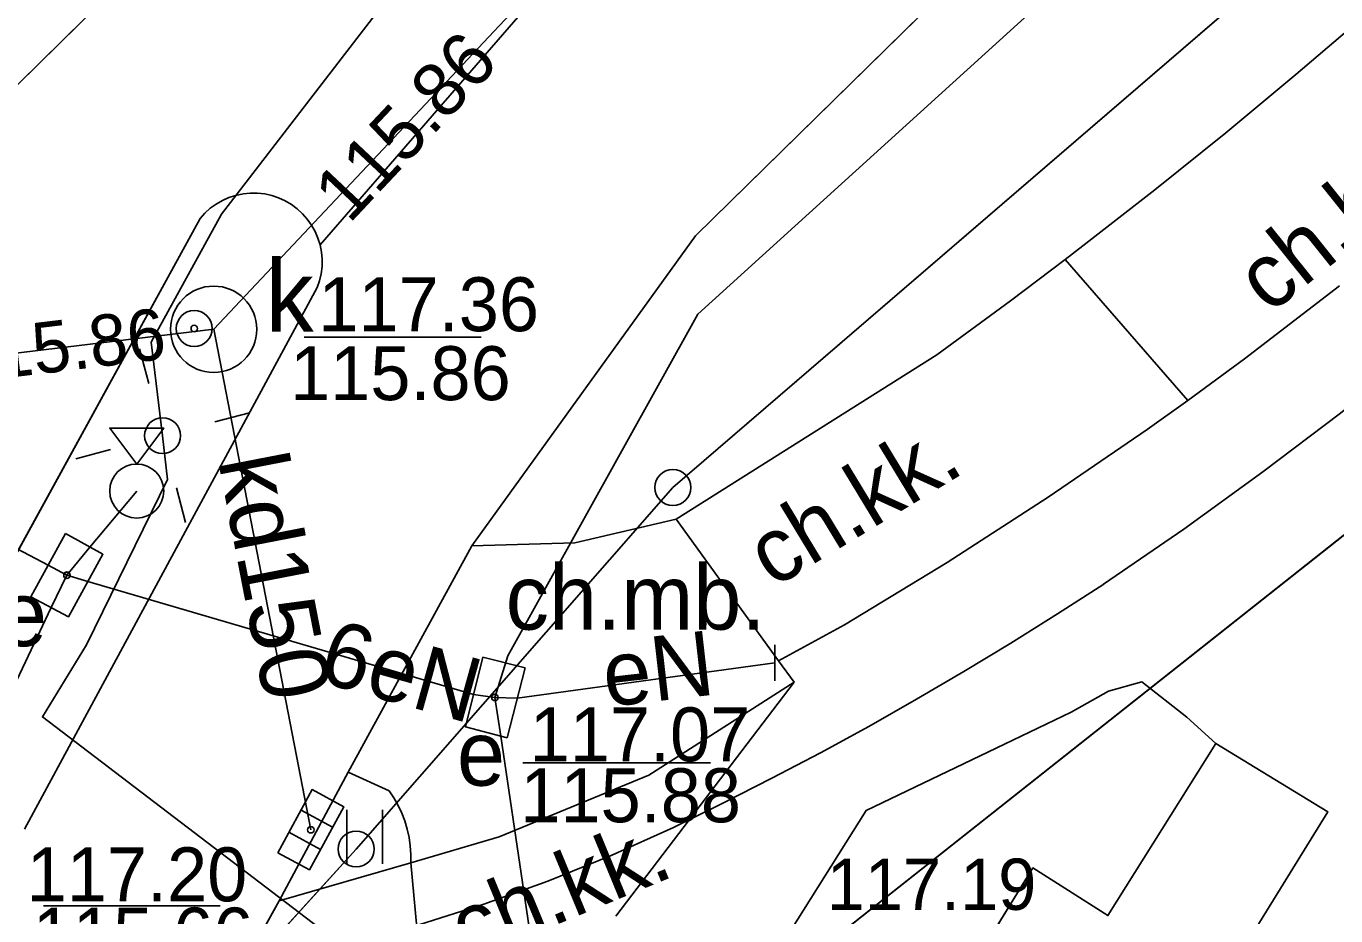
# Model space of a CAD drawing. Extents: x 6434771 to 6436222, y 5663454 to 5664782.
# Drawn here: x 6435500.32 to 6435518.53, y 5663756.44 to 5663768.81 of the extents above; entities that cross this region are included whole.
import ezdxf

# ---------------------------------------------------------------- set-up
doc = ezdxf.new("R2010")
doc.units = 0
for name, color, linetype in [('Warstwa 1', 7, 'Continuous'), ('Warstwa 10', 7, 'Continuous'), ('Warstwa 11', 7, 'Continuous'), ('Warstwa 12', 7, 'Continuous'), ('Warstwa 13', 7, 'Continuous'), ('Warstwa 14', 7, 'Continuous'), ('Warstwa 15', 7, 'Continuous'), ('Warstwa 2', 7, 'Continuous'), ('Warstwa 20', 7, 'Continuous'), ('Warstwa 37', 7, 'Continuous'), ('Warstwa 4', 7, 'Continuous'), ('Warstwa 40', 7, 'Continuous'), ('Warstwa 5', 7, 'Continuous'), ('Warstwa 6', 7, 'Continuous'), ('Warstwa 7', 7, 'Continuous'), ('Warstwa 8', 7, 'Continuous'), ('Warstwa 9', 7, 'Continuous')]:
    doc.layers.add(name, color=color, linetype=linetype)

msp = doc.modelspace()

# ---------------------------------------------------------------- linework, layer by layer
at = {"layer": 'Warstwa 1'}
for p, q in [((6435492.76, 5663760.678), (6435514.22, 5663781.8)), ((6435492.76, 5663760.678), (6435514.22, 5663781.8)), ((6435509.313, 5663762.399), (6435521.147, 5663772.588)), ((6435509.313, 5663762.399), (6435521.147, 5663772.588)), ((6435506.094, 5663751.807), (6435526.058, 5663767.608)), ((6435506.094, 5663751.807), (6435526.058, 5663767.608)), ((6435504.911, 5663757.372), (6435509.313, 5663762.399)), ((6435504.911, 5663757.372), (6435509.313, 5663762.399)), ((6435502.002, 5663754.167), (6435504.911, 5663757.372)), ((6435502.002, 5663754.167), (6435504.911, 5663757.372))]:
    msp.add_line(p, q, dxfattribs=at)
msp.add_lwpolyline([(6435511.034, 5663751.768), (6435514.319, 5663757.109), (6435515.361, 5663756.446), (6435516.861, 5663758.838), (6435518.419, 5663757.889), (6435513.645, 5663750.156)], close=True, dxfattribs=at)
at = {"layer": 'Warstwa 10'}
for centre in [(6435509.313, 5663762.399), (6435504.911, 5663757.372)]:
    msp.add_circle(centre, 0.25, dxfattribs=at)
at = {"layer": 'Warstwa 11'}
for points in [[(6435500.87, 5663761.76), (6435501.39, 5663761.47), (6435500.91, 5663760.6), (6435500.39, 5663760.88)], [(6435506.67, 5663760.04), (6435507.26, 5663759.89), (6435507.01, 5663758.92), (6435506.43, 5663759.07)]]:
    msp.add_lwpolyline(points, close=True, dxfattribs=at)
at = {"layer": 'Warstwa 12'}
for points in [[(6435506.84, 5663759.48), (6435507.02, 5663760.06), (6435509.66, 5663764.81), (6435538.22, 5663790.73)], [(6435519.85, 5663786.8), (6435515.54, 5663782.44), (6435503.04, 5663766.2), (6435502.06, 5663764.42), (6435502.22, 5663763.12), (6435502.29, 5663762.51), (6435501.16, 5663760.21), (6435500.55, 5663759.21), (6435505.86, 5663755.16), (6435506.73, 5663754.16), (6435505.81, 5663752.14)], [(6435492.06, 5663765.83), (6435500.63, 5663761.32), (6435500.89, 5663761.18)], [(6435500.89, 5663761.18), (6435501.21, 5663761.57), (6435501.86, 5663762.35)], [(6435500.89, 5663761.18), (6435500.67, 5663760.73), (6435499.47, 5663758.2)], [(6435506.84, 5663759.48), (6435506.54, 5663759.52), (6435501.18, 5663761.09), (6435500.89, 5663761.18)], [(6435506.84, 5663759.48), (6435507.15, 5663759.47), (6435510.73, 5663759.96)], [(6435535.28, 5663734.7), (6435527.228, 5663738.595), (6435523.88, 5663739.92), (6435523.02, 5663740.16), (6435522.22, 5663740.52), (6435517.92, 5663742.46), (6435512.14, 5663745.73), (6435509.95, 5663747.21), (6435508.87, 5663748.54), (6435508.28, 5663749.68), (6435507.77, 5663751.74), (6435507.02, 5663753.96), (6435507.56, 5663754.62), (6435506.92, 5663758.94), (6435506.84, 5663759.48)]]:
    msp.add_lwpolyline(points, dxfattribs=at)
at = {"layer": 'Warstwa 14'}
for p, q in [((6435504.186, 5663764.489), (6435506.649, 5663764.489)), ((6435500.566, 5663756.581), (6435503.018, 5663756.581))]:
    msp.add_line(p, q, dxfattribs=at)
msp.add_lwpolyline([(6435509.837, 5663758.572), (6435507.227, 5663758.572)], dxfattribs=at)
for centre in [(6435502.66, 5663764.61), (6435502.66, 5663764.61), (6435502.66, 5663764.61), (6435500.89, 5663761.18), (6435500.89, 5663761.18), (6435506.84, 5663759.48), (6435504.28, 5663757.64)]:
    msp.add_circle(centre, 0.045, dxfattribs=at)
at = {"layer": 'Warstwa 15'}
msp.add_circle((6435502.93, 5663764.6), 0.6, dxfattribs=at)
at = {"layer": 'Warstwa 2'}
msp.add_circle((6435502.22, 5663763.12), 0.25, dxfattribs=at)
at = {"layer": 'Warstwa 20'}
msp.add_line((6435510.73, 5663759.71), (6435510.73, 5663760.21), dxfattribs=at)
at = {"layer": 'Warstwa 37'}
for points in [[(6435524.604, 5663768.893), (6435523.66, 5663767.922), (6435522.692, 5663766.975), (6435521.701, 5663766.052), (6435520.687, 5663765.154), (6435519.652, 5663764.282), (6435518.595, 5663763.435), (6435517.517, 5663762.615), (6435516.419, 5663761.822), (6435515.302, 5663761.056)], [(6435515.303, 5663761.056), (6435514.661, 5663760.641), (6435514.014, 5663760.236), (6435513.36, 5663759.84), (6435512.701, 5663759.454), (6435512.036, 5663759.078), (6435511.366, 5663758.711), (6435510.69, 5663758.355), (6435510.009, 5663758.008), (6435509.323, 5663757.672)], [(6435509.323, 5663757.672), (6435508.457, 5663757.282), (6435507.577, 5663756.926), (6435506.684, 5663756.604), (6435505.78, 5663756.317), (6435504.865, 5663756.065), (6435503.94, 5663755.849), (6435503.009, 5663755.668), (6435502.071, 5663755.523), (6435501.128, 5663755.415)]]:
    msp.add_lwpolyline(points, dxfattribs=at)
at = {"layer": 'Warstwa 4'}
for p, q in [((6435504.144, 5663757.913), (6435504.583, 5663757.674)), ((6435503.977, 5663757.606), (6435504.416, 5663757.367))]:
    msp.add_line(p, q, dxfattribs=at)
for points in [[(6435502.028, 5663763.845), (6435501.9, 5663764.328)], [(6435502.945, 5663763.312), (6435503.428, 5663763.44)], [(6435501.495, 5663762.928), (6435501.012, 5663762.8)], [(6435502.412, 5663762.395), (6435502.54, 5663761.912)]]:
    msp.add_lwpolyline(points, dxfattribs=at)
for points in [[(6435500.87, 5663761.76), (6435501.39, 5663761.47), (6435500.91, 5663760.6), (6435500.39, 5663760.88)], [(6435506.67, 5663760.04), (6435507.26, 5663759.89), (6435507.01, 5663758.92), (6435506.43, 5663759.07)], [(6435503.821, 5663757.32), (6435504.299, 5663758.199), (6435504.739, 5663757.96), (6435504.261, 5663757.081)]]:
    msp.add_lwpolyline(points, close=True, dxfattribs=at)
msp.add_circle((6435502.66, 5663764.61), 0.25, dxfattribs=at)
at = {"layer": 'Warstwa 40'}
msp.add_lwpolyline([(6435501.86, 5663762.725), (6435501.485, 5663763.225), (6435502.235, 5663763.225)], close=True, dxfattribs=at)
msp.add_circle((6435501.86, 5663762.35), 0.375, dxfattribs=at)
at = {"layer": 'Warstwa 5'}
for p, q in [((6435503.84, 5663756.65), (6435504.8, 5663758.44)), ((6435504.8, 5663758.44), (6435505.37, 5663758.18)), ((6435505.37, 5663758.18), (6435505.436, 5663758.082)), ((6435505.436, 5663758.082), (6435505.494, 5663757.979)), ((6435504.779, 5663757.165), (6435504.779, 5663757.915)), ((6435505.279, 5663757.165), (6435505.279, 5663757.915)), ((6435505.494, 5663757.979), (6435505.544, 5663757.872)), ((6435505.544, 5663757.872), (6435505.587, 5663757.762)), ((6435505.587, 5663757.762), (6435505.621, 5663757.648)), ((6435505.621, 5663757.648), (6435505.646, 5663757.533)), ((6435505.646, 5663757.533), (6435505.663, 5663757.416)), ((6435505.663, 5663757.416), (6435505.671, 5663757.298)), ((6435505.67, 5663757.18), (6435505.671, 5663757.298)), ((6435503.84, 5663756.65), (6435505.67, 5663757.18))]:
    msp.add_line(p, q, dxfattribs=at)
at = {"layer": 'Warstwa 6'}
for points in [[(6435570.992, 5663837.121), (6435527.892, 5663795.248), (6435514.22, 5663781.8), (6435492.76, 5663760.678), (6435502.002, 5663754.167), (6435504.911, 5663757.372), (6435509.313, 5663762.399), (6435521.147, 5663772.588), (6435548.671, 5663800.788)], [(6435547.198, 5663801.229), (6435542.95, 5663796.915), (6435539.74, 5663793.64), (6435534.45, 5663788.61), (6435527.64, 5663782.4), (6435513.43, 5663769.63), (6435509.63, 5663765.9)], [(6435492.76, 5663760.678), (6435514.22, 5663781.8), (6435512.59, 5663782.25), (6435510.77, 5663783.65), (6435509.75, 5663785.12), (6435508.43, 5663787.33), (6435506.7, 5663789.56), (6435497.48, 5663799.45)], [(6435552.721, 5663796.629), (6435547.892, 5663795.057), (6435543.163, 5663791.864), (6435523.103, 5663770.554), (6435521.147, 5663772.588), (6435509.313, 5663762.399), (6435504.911, 5663757.372), (6435502.002, 5663754.167), (6435506.094, 5663751.807), (6435526.058, 5663767.608), (6435546.338, 5663788.935), (6435550.407, 5663791.326)], [(6435500.3, 5663757.65), (6435504.37, 5663765.18), (6435504.403, 5663765.275), (6435504.425, 5663765.373), (6435504.437, 5663765.473), (6435504.438, 5663765.574), (6435504.429, 5663765.674), (6435504.41, 5663765.773), (6435504.38, 5663765.869), (6435504.34, 5663765.961), (6435504.29, 5663766.049), (6435504.232, 5663766.131), (6435504.166, 5663766.207), (6435504.092, 5663766.275), (6435504.011, 5663766.335), (6435503.924, 5663766.386), (6435503.832, 5663766.427), (6435503.737, 5663766.459), (6435503.639, 5663766.481), (6435503.539, 5663766.492), (6435503.438, 5663766.492), (6435503.338, 5663766.483), (6435503.239, 5663766.462), (6435503.143, 5663766.431), (6435503.051, 5663766.391), (6435502.964, 5663766.341), (6435502.882, 5663766.282), (6435502.807, 5663766.215), (6435502.74, 5663766.14)], [(6435502.74, 5663766.14), (6435498.53, 5663758.46)], [(6435502.83, 5663754.83), (6435503.84, 5663756.65), (6435504.8, 5663758.44), (6435506.52, 5663761.59), (6435509.63, 5663765.9)], [(6435510.068, 5663749.932), (6435508.177, 5663751.095), (6435508.295, 5663751.365), (6435508.783, 5663752.16), (6435509.779, 5663754.251), (6435510.46, 5663755.36), (6435510.947, 5663756.236), (6435511.999, 5663757.906), (6435513.924, 5663758.828), (6435514.851, 5663759.276), (6435515.371, 5663759.569), (6435515.834, 5663759.697), (6435516.46, 5663759.205), (6435516.861, 5663758.838)]]:
    msp.add_lwpolyline(points, dxfattribs=at)
msp.add_lwpolyline([(6435557.506, 5663792.861), (6435553.992, 5663792.563), (6435550.407, 5663791.326), (6435546.338, 5663788.935), (6435526.058, 5663767.608), (6435506.094, 5663751.807), (6435529.689, 5663738.733), (6435568.207, 5663755.62), (6435573.888, 5663760.552), (6435577.803, 5663768.465), (6435578.155, 5663776.031), (6435574.677, 5663783.684), (6435569.533, 5663789.156), (6435561.733, 5663792.55)], close=True, dxfattribs=at)
for centre in [(6435502.66, 5663764.61), (6435500.89, 5663761.178), (6435506.84, 5663759.48), (6435504.28, 5663757.64)]:
    msp.add_circle(centre, 0.045, dxfattribs=at)
at = {"layer": 'Warstwa 7'}
for points in [[(6435514.4, 5663776.8), (6435502.93, 5663764.6)], [(6435502.93, 5663764.6), (6435492.88, 5663763.38)], [(6435502.93, 5663764.6), (6435504.28, 5663757.64)]]:
    msp.add_lwpolyline(points, dxfattribs=at)
at = {"layer": 'Warstwa 8'}
for p, q in [((6435504.41, 5663765.773), (6435511.831, 5663774.325)), ((6435504.41, 5663765.773), (6435511.831, 5663774.325)), ((6435509.63, 5663765.9), (6435513.43, 5663769.63)), ((6435503.051, 5663766.391), (6435503.143, 5663766.431)), ((6435503.143, 5663766.431), (6435503.239, 5663766.462)), ((6435503.239, 5663766.462), (6435503.338, 5663766.483)), ((6435503.338, 5663766.483), (6435503.438, 5663766.492)), ((6435503.438, 5663766.492), (6435503.539, 5663766.492)), ((6435503.539, 5663766.492), (6435503.639, 5663766.481)), ((6435503.639, 5663766.481), (6435503.737, 5663766.459)), ((6435503.737, 5663766.459), (6435503.832, 5663766.427)), ((6435503.832, 5663766.427), (6435503.924, 5663766.386)), ((6435502.74, 5663766.14), (6435502.807, 5663766.215)), ((6435502.807, 5663766.215), (6435502.882, 5663766.282)), ((6435502.882, 5663766.282), (6435502.964, 5663766.341)), ((6435502.964, 5663766.341), (6435503.051, 5663766.391)), ((6435503.924, 5663766.386), (6435504.011, 5663766.335)), ((6435504.011, 5663766.335), (6435504.092, 5663766.275)), ((6435504.092, 5663766.275), (6435504.166, 5663766.207)), ((6435498.53, 5663758.46), (6435502.74, 5663766.14)), ((6435504.166, 5663766.207), (6435504.232, 5663766.131)), ((6435504.232, 5663766.131), (6435504.29, 5663766.049)), ((6435504.29, 5663766.049), (6435504.34, 5663765.961)), ((6435504.34, 5663765.961), (6435504.38, 5663765.869)), ((6435504.38, 5663765.869), (6435504.41, 5663765.773)), ((6435506.52, 5663761.59), (6435509.63, 5663765.9)), ((6435504.41, 5663765.773), (6435504.429, 5663765.674)), ((6435504.429, 5663765.674), (6435504.438, 5663765.574)), ((6435504.437, 5663765.473), (6435504.438, 5663765.574)), ((6435504.403, 5663765.275), (6435504.425, 5663765.373)), ((6435504.425, 5663765.373), (6435504.437, 5663765.473)), ((6435500.3, 5663757.65), (6435504.37, 5663765.18)), ((6435504.37, 5663765.18), (6435504.403, 5663765.275)), ((6435504.8, 5663758.44), (6435506.52, 5663761.59)), ((6435515.371, 5663759.569), (6435515.834, 5663759.697)), ((6435515.834, 5663759.697), (6435516.46, 5663759.205)), ((6435514.851, 5663759.276), (6435515.371, 5663759.569)), ((6435513.924, 5663758.828), (6435514.851, 5663759.276)), ((6435516.46, 5663759.205), (6435516.861, 5663758.838)), ((6435511.999, 5663757.906), (6435513.924, 5663758.828)), ((6435515.361, 5663756.446), (6435516.861, 5663758.838)), ((6435503.84, 5663756.65), (6435504.8, 5663758.44)), ((6435510.947, 5663756.236), (6435511.999, 5663757.906)), ((6435511.034, 5663751.768), (6435514.319, 5663757.109)), ((6435514.319, 5663757.109), (6435515.361, 5663756.446)), ((6435502.83, 5663754.83), (6435503.84, 5663756.65))]:
    msp.add_line(p, q, dxfattribs=at)
at = {"layer": 'Warstwa 9'}
for p, q in [((6435517.974, 5663768.141), (6435518.937, 5663768.962)), ((6435516.999, 5663767.333), (6435517.974, 5663768.141)), ((6435516.012, 5663766.539), (6435516.999, 5663767.333)), ((6435515.014, 5663765.76), (6435516.012, 5663766.539)), ((6435514.769, 5663765.572), (6435515.014, 5663765.76)), ((6435514.005, 5663764.995), (6435514.769, 5663765.572)), ((6435514.769, 5663765.572), (6435516.471, 5663763.608)), ((6435514.769, 5663765.572), (6435516.471, 5663763.608)), ((6435517.258, 5663764.188), (6435518.582, 5663765.206)), ((6435512.985, 5663764.245), (6435514.005, 5663764.995)), ((6435509.36, 5663761.96), (6435512.985, 5663764.245)), ((6435516.471, 5663763.608), (6435517.258, 5663764.188)), ((6435515.907, 5663763.207), (6435516.471, 5663763.608)), ((6435514.53, 5663762.263), (6435515.907, 5663763.207)), ((6435513.127, 5663761.357), (6435514.53, 5663762.263)), ((6435507.95, 5663761.63), (6435509.36, 5663761.96)), ((6435509.36, 5663761.96), (6435510.784, 5663759.989)), ((6435509.36, 5663761.96), (6435510.784, 5663759.989)), ((6435504.8, 5663758.44), (6435506.52, 5663761.59)), ((6435506.52, 5663761.59), (6435507.95, 5663761.63)), ((6435511.7, 5663760.49), (6435513.127, 5663761.357)), ((6435510.784, 5663759.989), (6435511.7, 5663760.49)), ((6435510.784, 5663759.989), (6435511, 5663759.69)), ((6435508.52, 5663756.44), (6435511, 5663759.69)), ((6435508.98, 5663758.4), (6435511, 5663759.69)), ((6435508.98, 5663758.4), (6435511, 5663759.69)), ((6435504.8, 5663758.44), (6435505.37, 5663758.18)), ((6435506.9, 5663757.54), (6435508.98, 5663758.4)), ((6435506.9, 5663757.54), (6435508.98, 5663758.4)), ((6435505.37, 5663758.18), (6435505.436, 5663758.082)), ((6435505.436, 5663758.082), (6435505.494, 5663757.979)), ((6435505.494, 5663757.979), (6435505.544, 5663757.872)), ((6435505.544, 5663757.872), (6435505.587, 5663757.762)), ((6435505.587, 5663757.762), (6435505.621, 5663757.648)), ((6435505.621, 5663757.648), (6435505.646, 5663757.533)), ((6435505.646, 5663757.533), (6435505.663, 5663757.416)), ((6435505.67, 5663757.18), (6435506.9, 5663757.54)), ((6435505.67, 5663757.18), (6435506.9, 5663757.54)), ((6435505.663, 5663757.416), (6435505.671, 5663757.298)), ((6435505.67, 5663757.18), (6435505.671, 5663757.298)), ((6435503.84, 5663756.65), (6435505.67, 5663757.18)), ((6435505.67, 5663757.18), (6435505.83, 5663755.5)), ((6435505.67, 5663757.18), (6435505.83, 5663755.5)), ((6435502.83, 5663754.83), (6435503.84, 5663756.65))]:
    msp.add_line(p, q, dxfattribs=at)

# ---------------------------------------------------------------- texts
at = {"layer": 'Warstwa 13'}
for s, rotation, p in [('6eN', 344.382, (6435504.356, 5663759.711)), ('eN', 6.4859, (6435508.39, 5663759.348))]:
    msp.add_text(s, height=0.9, rotation=rotation, dxfattribs=at).set_placement(p)
at = {"layer": 'Warstwa 14'}
for height, rotation, p in [(0.75, 46.7648, (6435504.813, 5663766.056)), (0.7125, 6.9213, (6435499.4, 5663763.843))]:
    msp.add_text('115.86', height=height, rotation=rotation, dxfattribs=at).set_placement(p)
for s, p in [('115.86', (6435503.992, 5663763.614)), ('115.88', (6435507.193, 5663757.744)), ('115.66', (6435500.413, 5663755.807))]:
    msp.add_text(s, height=0.75, dxfattribs=at).set_placement(p)
at = {"layer": 'Warstwa 5'}
for s, height, p in [('k', 1, (6435503.653, 5663764.565)), ('e', 0.9, (6435499.945, 5663760.193)), ('e', 0.9, (6435506.312, 5663758.253))]:
    msp.add_text(s, height=height, dxfattribs=at).set_placement(p)
at = {"layer": 'Warstwa 6'}
for s, height, p in [('117.36', 0.75, (6435504.385, 5663764.573)), ('117.07', 0.75, (6435507.322, 5663758.591)), ('117.20', 0.75, (6435500.33, 5663756.645)), ('117.19', 0.7125, (6435511.452, 5663756.526))]:
    msp.add_text(s, height=height, dxfattribs=at).set_placement(p)
at = {"layer": 'Warstwa 7'}
msp.add_text('kd150', height=0.95, rotation=280.9785, dxfattribs=at).set_placement((6435502.989, 5663762.777))
at = {"layer": 'Warstwa 9'}
for s, rotation, p in [('ch.bt.', 38.7377, (6435517.606, 5663764.798)), ('ch.kk.', 31.2147, (6435510.706, 5663760.991)), ('ch.kk.', 22.4657, (6435506.453, 5663755.804))]:
    msp.add_text(s, height=0.9, rotation=rotation, dxfattribs=at).set_placement(p)
msp.add_text('ch.mb.', height=0.9, dxfattribs=at).set_placement((6435506.989, 5663760.423))

doc.saveas('drawing.dxf')
